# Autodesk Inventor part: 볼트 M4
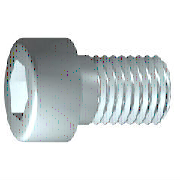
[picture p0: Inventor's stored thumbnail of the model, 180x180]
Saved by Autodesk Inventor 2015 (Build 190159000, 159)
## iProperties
IsCustomPart: 0
Created: 2009-02
Part Number: 볼트 M4
Material: 강철, 연강
Description: 6각머리 태핑 나사
Document SubType Name: Modeling
Standard: KS B 1003
Standards Organization: KS
Language: ko-KR
Size Designation: M 4 x 12
Categories: <MemberInstance><Categories><Category DisplayName="조임쇠" InternalName="e4da775c-781d-43d5-af7c-5136215cf5a6" Mnemonic="FSTN"><Category DisplayName="볼트" InternalN
Density: 1 g/cm^3
Appearance: 차가운 흰색
Author: pww
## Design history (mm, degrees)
sketch "스케치1"
  geometry: L1 (-1, 0)-(12, 0); L2 (12, 0)-(12, 2); L3 (12, 2)-(1.75, 2); L4 (1.75, 2)-(1.32, 2); L5 (1.32, 2)-(0, 2); L6 (0, 2)-(0, 3.5); L7 (0, 3.5)-(-4, 3.5); L8 (-4, 3.5)-(-4, 1.732); L9 (-4, 1.732)-(-2, 1.732); L10 (-2, 1.732)-(-1, 0); L11 (-7.2, 0)-(15.2, 0) reference; L12 (0, -0.7)-(0, 4.2) reference; L13 (1.75, 2)-(0, 2)
  constraints: 22 end point, 6 parallel, 2 collinear, 2 perpendicular, 1 horizontal, 1 point on line
  dimensions: "d1" = 10.25 distance from line of L3.end L2 (= GEL); "d2" = 0.42952 distance of L4.end L3.end (computed from GAL); "d3" = 4 distance between parallel lines of L8 L6 (= KOH); "d4" = 2 distance of L8.end L9.end (= INTI); "d5" = 60 deg angle of L10 L1; "d6" = 4 diameter of L3 L1 (= GD); "d7" = 4 diameter of L5 L1 (= BDM); "d8" = 3.4641 diameter of L9 L1 (= 1.1547 x SW); "d9" = 7 diameter of L7 L1 (= KOD); "d26" = 12 distance between parallel lines of L12 L2 (= NLG)
revolve "본체" sketch "스케치1" stored, may be unused: angle "d10" = 90 deg
sketch "스케치2"
  geometry: L1 (0, -4.9)-(0, 4.9) reference; L2 (-4.9, 0)-(4.9, 0) reference; L3 (1.732, 0)-(0.866, -1.5); L4 (0.866, -1.5)-(-0.866, -1.5); L5 (-0.866, -1.5)-(-1.732, 0); L6 (-1.732, 0)-(-0.866, 1.5); L7 (-0.866, 1.5)-(0.866, 1.5); L8 (0.866, 1.5)-(1.732, 0); 2 further points
  constraints: 12 end point, 1 coincident, 1 horizontal alignment, 1 point on line, 12 other
extrude "슬롯" join sketch "스케치2" stored distance "d11" = 10; taper "d12" = 0 deg
workplane "Work Plane1"
fillet "Fillet2" dims "d30" = 0.1 (= R)
body "Solid1"
fillet "모깎기1" dims "d17" = 0.4 (= RR)
feature "스레드" dims "d13" = 10.25 (= GEL), "d14" = 0
chamfer "모따기1" distance "d15" = 0.42941 (= -0.5 x SPD + 0.5 x GD); stored, may be unused: second distance "d16" = 0.42941 (= GUL), angle "d27" = 45 deg
other parameters: "GD" = 4 (= NND) [user parameter; used in 2 equation terms], "NLG" = 12 [user parameter; used in 1 equation term], "GEL" = 10.25 [user parameter; used in 2 equation terms], "KOD" = 7 [user parameter; used in 1 equation term], "KOH" = 4 [user parameter; used in 1 equation term], "INTI" = 2 [user parameter; used in 1 equation term], "GAL" = 0.42941 (= 0.61345 x PTC) [user parameter; used in 1 equation term], "GUL" = 0.42941 (= 0.61345 x PTC) [user parameter; used in 1 equation term], "BDM" = 4 (= NND) [user parameter; used in 1 equation term], "SW" = 3 [user parameter; used in 2 equation terms], "RR" = 0.4 [user parameter; used in 1 equation term], "SPD" = 3.14117 (= NND - 1.2269 x PTC) [user parameter; used in 1 equation term], "d19" = 0, "d28" = 0, "d29" = 0, "R" = 0.1 [user parameter; used in 1 equation term], "PHH" = 0.2 [user parameter], "GD1" = 3.14117 (= THREADDIA - 1.2269 x PTC) [user parameter], "THREADDIA" = 4 [user parameter; used in 1 equation term], "FAWI" = 45 deg [user parameter], "TPU" = 14.28571 (computed from PTC) [user parameter], "PTC" = 0.7 [user parameter; used in 5 equation terms], "NND" = 4 [user parameter; used in 3 equation terms], "TOA" = 30 deg [user parameter], "E0" = 3.465 (= 1.155 x SW) [user parameter]
